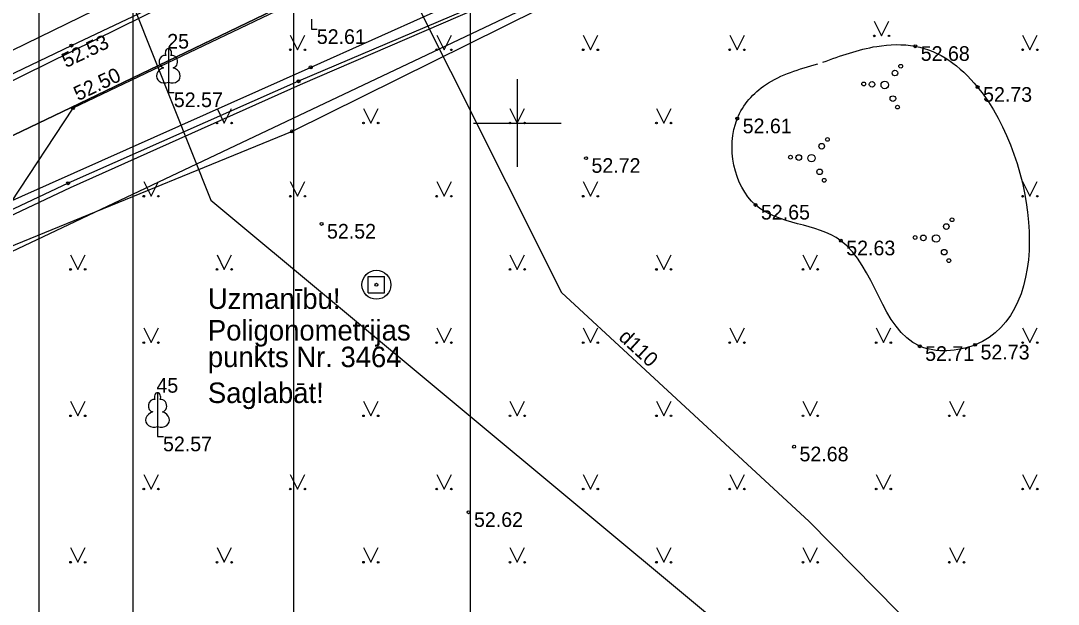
# Model space of a CAD drawing. Extents: x 619806 to 620082, y 405176 to 405386.
# Drawn here: x 619933.05 to 619968.46, y 405333.56 to 405353.49 of the extents above; entities that cross this region are included whole.
import ezdxf

# ---------------------------------------------------------------- set-up
doc = ezdxf.new("R2010")
doc.units = 0
for name, color, linetype in [('24', 7, 'Continuous'), ('APGR_SARK_####_####_#', 7, 'Continuous'), ('APGS_VADP_ZSPR_####_#', 7, 'Continuous'), ('CELI_CMAL_####_####_#', 7, 'Continuous'), ('ELEK_VADP_ZSPR_####_#', 7, 'Continuous'), ('GEOD_ELEM_####_####_#', 7, 'Continuous'), ('GEOD_ELEM_####_TKST_#', 7, 'Continuous'), ('RAMI_PLAN_####_TKST_#', 7, 'Continuous'), ('RAMI_UZMR_####_####_#', 7, 'Continuous'), ('RELJ_AATZ_####_TKST_#', 7, 'Continuous'), ('RELJ_ELEM_####_####_#', 7, 'Continuous'), ('ROBZ_UZMR_####_####_#', 7, 'Continuous'), ('SAKT_VADP_KABE_####_#', 7, 'Continuous'), ('TERT_DIAM_####_TKST_#', 7, 'Continuous'), ('TERT_ELEM_####_####_#', 7, 'Continuous'), ('TERT_KONT_####_####_#', 7, 'Continuous'), ('UDTK_VADP_UDEN_####_#', 7, 'Continuous'), ('UDTK_VADP_UDEN_TKST_#', 7, 'Continuous')]:
    doc.layers.add(name, color=color, linetype=linetype)

msp = doc.modelspace()

# ---------------------------------------------------------------- linework, layer by layer
at = {"layer": '24'}
for p, q in [((619962.326, 405363.803), (619934.749, 405350.522)), ((619934.749, 405350.522), (619931.837, 405349.12))]:
    msp.add_line(p, q, dxfattribs=at)
at = {"layer": 'APGR_SARK_####_####_#'}
msp.add_lwpolyline([(619818.56, 405291.467), (619964.609, 405360.731), (619976.198, 405343.424)], dxfattribs=at)
at = {"layer": 'APGS_VADP_ZSPR_####_#'}
for points in [[(619961.504, 405361.726), (619961.549, 405360.889), (619955.561, 405357.47), (619948.629, 405353.911), (619942.586, 405351.309), (619934.737, 405347.784), (619926.308, 405343.807), (619921.62, 405341.722), (619914.616, 405338.589), (619904.064, 405332.419), (619892.947, 405327.707), (619882.253, 405322.432), (619872.343, 405318.394), (619866.043, 405315.914), (619858.147, 405313.031), (619849.141, 405308.474), (619837.591, 405302.476), (619829.867, 405298.738), (619827.533, 405297.619), (619826.332, 405294.789), (619825.868, 405290.973), (619826.009, 405290.873), (619827.279, 405290.766)], [(619961.504, 405361.726), (619961.582, 405360.944), (619961.547, 405359.255), (619942.312, 405349.715), (619925.4, 405342.794), (619907.997, 405333.971), (619887.51, 405324.581), (619867.415, 405316.417), (619859.827, 405308.06), (619845.28, 405301.51), (619837.164, 405301.798), (619827.1, 405298.963), (619826.475, 405294.709), (619826.025, 405290.988), (619827.279, 405290.766)], [(619961.504, 405361.726), (619961.513, 405360.941), (619956.997, 405358.363), (619948.588, 405354.007), (619942.536, 405351.427), (619934.667, 405347.943), (619926.276, 405343.988), (619921.568, 405341.876), (619914.639, 405338.805), (619913.878, 405339.748), (619914.447, 405338.686), (619904.019, 405332.565), (619892.911, 405327.951)]]:
    msp.add_lwpolyline(points, dxfattribs=at)
at = {"layer": 'CELI_CMAL_####_####_#'}
for points in [[(619991.854, 405321.355), (619987.265, 405327.894), (619980.195, 405338.024), (619973.089, 405348.264), (619967.033, 405357.029), (619962.383, 405363.658), (619953.25, 405359.322), (619947.967, 405356.794), (619934.832, 405350.507), (619928.431, 405340.813), (619925.67, 405336.505), (619926.565, 405335.935), (619923.8, 405331.651)], [(619825.042, 405301.626), (619825.997, 405300.736), (619826.865, 405300.888), (619837.411, 405305.982), (619845.924, 405310.094), (619856.691, 405315.252), (619868.203, 405320.761), (619880.848, 405326.828), (619891.162, 405331.79), (619903.487, 405337.685), (619914.792, 405343.079), (619924.282, 405347.611), (619934.782, 405352.643), (619943.391, 405356.735), (619942.998, 405357.499)]]:
    msp.add_lwpolyline(points, dxfattribs=at)
at = {"layer": 'ELEK_VADP_ZSPR_####_#'}
msp.add_lwpolyline([(619971.958, 405366.357), (619953.365, 405356.579), (619942.947, 405351.901), (619927.707, 405345.105), (619922.312, 405345.694), (619917.565, 405346.118)], dxfattribs=at)
at = {"layer": 'GEOD_ELEM_####_####_#'}
for p, q in [((619950, 405351.5), (619950, 405350)), ((619948.5, 405350), (619950, 405350)), ((619950, 405350), (619950, 405348.5)), ((619950, 405350), (619951.5, 405350)), ((619944.909, 405344.756), (619945.47, 405344.756)), ((619944.909, 405344.195), (619944.909, 405344.756)), ((619945.47, 405344.195), (619945.47, 405344.756)), ((619944.909, 405344.195), (619945.47, 405344.195))]:
    msp.add_line(p, q, dxfattribs=at)
for radius in [0.495, 0.05]:
    msp.add_circle((619945.19, 405344.475), radius, dxfattribs=at)
at = {"layer": 'RAMI_PLAN_####_TKST_#'}
msp.add_line((619942.357, 405361.716), (619942.357, 405215.404), dxfattribs=at)
for points in [[(619933.685, 405385.595), (620082.185, 405385.595), (620082.185, 405175.595), (619933.685, 405175.595)], [(619805.793, 405180.095), (619805.793, 405373.209), (619948.393, 405373.209), (619948.393, 405180.095)], [(619936.885, 405180.095), (619936.885, 405373.209), (620079.485, 405373.209), (620079.485, 405180.095)]]:
    msp.add_lwpolyline(points, close=True, dxfattribs=at)
at = {"layer": 'RAMI_UZMR_####_####_#'}
msp.add_lwpolyline([(619874.687, 405324.979), (619926.719, 405349.544), (619966.669, 405369.042), (620021.738, 405292.03), (620049.703, 405275.476), (620026.189, 405242.287), (620012.147, 405222.917), (619996.603, 405200.928), (619989.997, 405199.173), (619982.328, 405199.155), (619922.669, 405233.014), (619882.137, 405255.756), (619859.084, 405268.056), (619820.646, 405290.715), (619813.744, 405295.206), (619820.645, 405298.752)], close=True, dxfattribs=at)
at = {"layer": 'RELJ_ELEM_####_####_#'}
for centre in [(619934.782, 405352.643), (619963.585, 405352.623), (619942.947, 405351.901), (619942.536, 405351.427), (619965.713, 405351.226), (619934.832, 405350.507), (619957.508, 405350.15), (619942.312, 405349.715), (619952.346, 405348.799), (619934.667, 405347.943), (619958.131, 405347.204), (619943.318, 405346.554), (619961.043, 405345.982), (619963.736, 405342.377), (619965.627, 405342.425), (619959.447, 405338.946), (619948.336, 405336.706)]:
    msp.add_circle(centre, 0.05, dxfattribs=at)
at = {"layer": 'ROBZ_UZMR_####_####_#'}
for p, q in [((619934.749, 405350.522), (619962.326, 405363.803)), ((619931.837, 405349.12), (619934.749, 405350.522))]:
    msp.add_line(p, q, dxfattribs=at)
at = {"layer": 'SAKT_VADP_KABE_####_#'}
for points in [[(619816.151, 405294.73), (619838.42, 405305.23), (619866.149, 405318.697), (619899.278, 405334.929), (619937.202, 405353.635), (619962.924, 405366.289), (619964.424, 405369.208)], [(619935.629, 405357.201), (619939.538, 405347.363), (619973.032, 405319.457), (620006.975, 405291.595), (620036.262, 405267.248), (620043.553, 405261.241)]]:
    msp.add_lwpolyline(points, dxfattribs=at)
at = {"layer": 'TERT_ELEM_####_####_#'}
for p, q in [((619942.971, 405353.548), (619942.971, 405353.201)), ((619962.186, 405353.476), (619962.436, 405352.976)), ((619962.436, 405352.976), (619962.686, 405353.476)), ((619942.971, 405353.201), (619943.171, 405353.201)), ((619942.25, 405353), (619942.5, 405352.5)), ((619942.5, 405352.5), (619942.75, 405353)), ((619947.25, 405353), (619947.5, 405352.5)), ((619947.5, 405352.5), (619947.75, 405353)), ((619952.25, 405353), (619952.5, 405352.5)), ((619952.5, 405352.5), (619952.75, 405353)), ((619957.25, 405353), (619957.5, 405352.5)), ((619957.5, 405352.5), (619957.75, 405353)), ((619967.25, 405353), (619967.5, 405352.5)), ((619967.5, 405352.5), (619967.75, 405353)), ((619938.09, 405351.39), (619938.09, 405351.043)), ((619938.09, 405351.043), (619938.29, 405351.043)), ((619939.75, 405350.5), (619940, 405350)), ((619940, 405350), (619940.25, 405350.5)), ((619944.75, 405350.5), (619945, 405350)), ((619945, 405350), (619945.25, 405350.5)), ((619949.75, 405350.5), (619950, 405350)), ((619950, 405350), (619950.25, 405350.5)), ((619954.75, 405350.5), (619955, 405350)), ((619955, 405350), (619955.25, 405350.5)), ((619937.25, 405348), (619937.5, 405347.5)), ((619937.5, 405347.5), (619937.75, 405348)), ((619942.25, 405348), (619942.5, 405347.5)), ((619942.5, 405347.5), (619942.75, 405348)), ((619947.25, 405348), (619947.5, 405347.5)), ((619947.5, 405347.5), (619947.75, 405348)), ((619952.25, 405348), (619952.5, 405347.5)), ((619952.5, 405347.5), (619952.75, 405348)), ((619967.25, 405348), (619967.5, 405347.5)), ((619967.5, 405347.5), (619967.75, 405348)), ((619934.75, 405345.5), (619935, 405345)), ((619935, 405345), (619935.25, 405345.5)), ((619939.75, 405345.5), (619940, 405345)), ((619940, 405345), (619940.25, 405345.5)), ((619949.75, 405345.5), (619950, 405345)), ((619950, 405345), (619950.25, 405345.5)), ((619954.75, 405345.5), (619955, 405345)), ((619955, 405345), (619955.25, 405345.5)), ((619959.75, 405345.5), (619960, 405345)), ((619960, 405345), (619960.25, 405345.5)), ((619937.25, 405343), (619937.5, 405342.5)), ((619937.5, 405342.5), (619937.75, 405343)), ((619947.25, 405343), (619947.5, 405342.5)), ((619947.5, 405342.5), (619947.75, 405343)), ((619952.25, 405343), (619952.5, 405342.5)), ((619952.5, 405342.5), (619952.75, 405343)), ((619957.25, 405343), (619957.5, 405342.5)), ((619957.5, 405342.5), (619957.75, 405343)), ((619962.25, 405343), (619962.5, 405342.5)), ((619962.5, 405342.5), (619962.75, 405343)), ((619967.25, 405343), (619967.5, 405342.5)), ((619967.5, 405342.5), (619967.75, 405343)), ((619934.75, 405340.5), (619935, 405340)), ((619935, 405340), (619935.25, 405340.5)), ((619944.75, 405340.5), (619945, 405340)), ((619945, 405340), (619945.25, 405340.5)), ((619949.75, 405340.5), (619950, 405340)), ((619950, 405340), (619950.25, 405340.5)), ((619954.75, 405340.5), (619955, 405340)), ((619955, 405340), (619955.25, 405340.5)), ((619959.75, 405340.5), (619960, 405340)), ((619960, 405340), (619960.25, 405340.5)), ((619964.75, 405340.5), (619965, 405340)), ((619965, 405340), (619965.25, 405340.5)), ((619937.721, 405339.637), (619937.721, 405339.29)), ((619937.721, 405339.29), (619937.921, 405339.29)), ((619937.25, 405338), (619937.5, 405337.5)), ((619937.5, 405337.5), (619937.75, 405338)), ((619942.25, 405338), (619942.5, 405337.5)), ((619942.5, 405337.5), (619942.75, 405338)), ((619947.25, 405338), (619947.5, 405337.5)), ((619947.5, 405337.5), (619947.75, 405338)), ((619952.25, 405338), (619952.5, 405337.5)), ((619952.5, 405337.5), (619952.75, 405338)), ((619957.25, 405338), (619957.5, 405337.5)), ((619957.5, 405337.5), (619957.75, 405338)), ((619962.25, 405338), (619962.5, 405337.5)), ((619962.5, 405337.5), (619962.75, 405338)), ((619967.25, 405338), (619967.5, 405337.5)), ((619967.5, 405337.5), (619967.75, 405338)), ((619934.75, 405335.5), (619935, 405335)), ((619935, 405335), (619935.25, 405335.5)), ((619939.75, 405335.5), (619940, 405335)), ((619940, 405335), (619940.25, 405335.5)), ((619944.75, 405335.5), (619945, 405335)), ((619945, 405335), (619945.25, 405335.5)), ((619949.75, 405335.5), (619950, 405335)), ((619950, 405335), (619950.25, 405335.5)), ((619954.75, 405335.5), (619955, 405335)), ((619955, 405335), (619955.25, 405335.5)), ((619959.75, 405335.5), (619960, 405335)), ((619960, 405335), (619960.25, 405335.5)), ((619964.75, 405335.5), (619965, 405335)), ((619965, 405335), (619965.25, 405335.5))]:
    msp.add_line(p, q, dxfattribs=at)
for points in [[(619938.09, 405352.543), (619938.09, 405351.39)], [(619938.18, 405352.311), (619938.179, 405352.312)], [(619937.721, 405340.79), (619937.721, 405339.637)], [(619937.811, 405340.558), (619937.81, 405340.559)]]:
    msp.add_lwpolyline(points, dxfattribs=at)
for centre, radius in [((619962.186, 405352.976), 0.028), ((619962.686, 405352.976), 0.0263), ((619942.25, 405352.5), 0.028), ((619942.75, 405352.5), 0.0263), ((619947.25, 405352.5), 0.028), ((619947.75, 405352.5), 0.0263), ((619952.25, 405352.5), 0.028), ((619952.75, 405352.5), 0.0263), ((619957.25, 405352.5), 0.028), ((619957.75, 405352.5), 0.0263), ((619967.25, 405352.5), 0.028), ((619967.75, 405352.5), 0.0263), ((619963.087, 405351.939), 0.064), ((619962.891, 405351.707), 0.096), ((619961.825, 405351.334), 0.064), ((619962.109, 405351.321), 0.096), ((619962.543, 405351.3), 0.128), ((619962.82, 405350.833), 0.096), ((619962.977, 405350.544), 0.064), ((619939.75, 405350), 0.028), ((619940.25, 405350), 0.0263), ((619944.75, 405350), 0.028), ((619945.25, 405350), 0.0263), ((619949.75, 405350), 0.028), ((619950.25, 405350), 0.0263), ((619954.75, 405350), 0.028), ((619955.25, 405350), 0.0263), ((619960.587, 405349.439), 0.064), ((619960.391, 405349.207), 0.096), ((619959.325, 405348.834), 0.064), ((619959.609, 405348.821), 0.096), ((619960.043, 405348.8), 0.128), ((619960.32, 405348.333), 0.096), ((619960.477, 405348.044), 0.064), ((619937.25, 405347.5), 0.028), ((619937.75, 405347.5), 0.0263), ((619942.25, 405347.5), 0.028), ((619942.75, 405347.5), 0.0263), ((619947.25, 405347.5), 0.028), ((619947.75, 405347.5), 0.0263), ((619952.25, 405347.5), 0.028), ((619952.75, 405347.5), 0.0263), ((619967.25, 405347.5), 0.028), ((619967.75, 405347.5), 0.0263), ((619964.84, 405346.696), 0.064), ((619964.644, 405346.465), 0.096), ((619963.578, 405346.091), 0.064), ((619963.862, 405346.078), 0.096), ((619964.296, 405346.057), 0.128), ((619964.572, 405345.59), 0.096), ((619964.73, 405345.301), 0.064), ((619934.75, 405345), 0.028), ((619935.25, 405345), 0.0263), ((619939.75, 405345), 0.028), ((619940.25, 405345), 0.0263), ((619949.75, 405345), 0.028), ((619950.25, 405345), 0.0263), ((619954.75, 405345), 0.028), ((619955.25, 405345), 0.0263), ((619959.75, 405345), 0.028), ((619960.25, 405345), 0.0263), ((619937.25, 405342.5), 0.028), ((619937.75, 405342.5), 0.0263), ((619947.25, 405342.5), 0.028), ((619947.75, 405342.5), 0.0263), ((619952.25, 405342.5), 0.028), ((619952.75, 405342.5), 0.0263), ((619957.25, 405342.5), 0.028), ((619957.75, 405342.5), 0.0263), ((619962.25, 405342.5), 0.028), ((619962.75, 405342.5), 0.0263), ((619967.25, 405342.5), 0.028), ((619967.75, 405342.5), 0.0263), ((619934.75, 405340), 0.028), ((619935.25, 405340), 0.0263), ((619944.75, 405340), 0.028), ((619945.25, 405340), 0.0263), ((619949.75, 405340), 0.028), ((619950.25, 405340), 0.0263), ((619954.75, 405340), 0.028), ((619955.25, 405340), 0.0263), ((619959.75, 405340), 0.028), ((619960.25, 405340), 0.0263), ((619964.75, 405340), 0.028), ((619965.25, 405340), 0.0263), ((619937.25, 405337.5), 0.028), ((619937.75, 405337.5), 0.0263), ((619942.25, 405337.5), 0.028), ((619942.75, 405337.5), 0.0263), ((619947.25, 405337.5), 0.028), ((619947.75, 405337.5), 0.0263), ((619952.25, 405337.5), 0.028), ((619952.75, 405337.5), 0.0263), ((619957.25, 405337.5), 0.028), ((619957.75, 405337.5), 0.0263), ((619962.25, 405337.5), 0.028), ((619962.75, 405337.5), 0.0263), ((619967.25, 405337.5), 0.028), ((619967.75, 405337.5), 0.0263), ((619934.75, 405335), 0.028), ((619935.25, 405335), 0.0263), ((619939.75, 405335), 0.028), ((619940.25, 405335), 0.0263), ((619944.75, 405335), 0.028), ((619945.25, 405335), 0.0263), ((619949.75, 405335), 0.028), ((619950.25, 405335), 0.0263), ((619954.75, 405335), 0.028), ((619955.25, 405335), 0.0263), ((619959.75, 405335), 0.028), ((619960.25, 405335), 0.0263), ((619964.75, 405335), 0.028), ((619965.25, 405335), 0.0263)]:
    msp.add_circle(centre, radius, dxfattribs=at)
for centre, major_axis, ratio, start_param, end_param in [((619937.962, 405352.098), (-0.039, -0.212), 0.861323, 3.141593, 6.283185), ((619938.09, 405352.393), (0, -0.15), 0.707107, 3.14537, 5.287485), ((619938.09, 405352.393), (0, -0.15), 0.707107, 0.995701, 3.137816), ((619938.218, 405352.098), (0.039, -0.212), 0.861323, 0, 3.141593), ((619938, 405351.636), (0.307, 0.095), 0.814445, 1.570796, 4.752015), ((619938.18, 405351.636), (-0.307, 0.095), 0.814445, 1.531171, 4.712389), ((619937.721, 405340.64), (0, -0.15), 0.707107, 3.14537, 5.287485), ((619937.721, 405340.64), (0, -0.15), 0.707107, 0.995701, 3.137816), ((619937.593, 405340.345), (-0.039, -0.212), 0.861323, 3.141593, 6.283185), ((619937.849, 405340.345), (0.039, -0.212), 0.861323, 0, 3.141593), ((619937.631, 405339.883), (0.307, 0.095), 0.814445, 1.570796, 4.752015), ((619937.811, 405339.883), (-0.307, 0.095), 0.814445, 1.531171, 4.712389)]:
    msp.add_ellipse(centre, major_axis=major_axis, ratio=ratio, start_param=start_param, end_param=end_param, dxfattribs=at)
at = {"layer": 'TERT_KONT_####_####_#'}
msp.add_spline([(619960.429, 405352.076), (619962.267, 405352.617), (619963.585, 405352.623), (619965.713, 405351.226), (619965.627, 405342.425), (619963.736, 405342.377), (619961.043, 405345.982), (619958.131, 405347.204), (619957.508, 405350.15), (619958.477, 405351.308), (619960.254, 405352.018)], degree=3, dxfattribs=at)
at = {"layer": 'UDTK_VADP_UDEN_####_#'}
msp.add_lwpolyline([(619945.834, 405355.555), (619951.504, 405344.209), (619959.966, 405336.395), (619975.103, 405321.007), (620000.001, 405300.143)], dxfattribs=at)

# ---------------------------------------------------------------- texts
at = {"layer": 'GEOD_ELEM_####_TKST_#'}
for s, p in [('Uzmanību!', (619939.439, 405343.652)), ('Poligonometrijas', (619939.439, 405342.572)), ('punkts Nr. 3464', (619939.439, 405341.662)), ('Saglabāt!', (619939.439, 405340.437))]:
    msp.add_text(s, height=0.7, dxfattribs=at).set_placement(p)
at = {"layer": 'RELJ_AATZ_####_TKST_#'}
for s, p in [(' 52.61', (619942.971, 405352.701)), (' 52.68', (619963.585, 405352.123)), (' 52.57', (619938.09, 405350.543)), (' 52.73', (619965.713, 405350.726)), (' 52.61', (619957.508, 405349.65)), (' 52.72', (619952.346, 405348.299)), (' 52.65', (619958.131, 405346.704)), (' 52.52', (619943.318, 405346.054)), (' 52.63', (619961.043, 405345.482)), (' 52.73', (619965.627, 405341.925)), (' 52.71', (619963.736, 405341.877)), (' 52.57', (619937.721, 405338.79)), (' 52.68', (619959.447, 405338.446)), (' 52.62', (619948.336, 405336.206))]:
    msp.add_text(s, height=0.5, dxfattribs=at).set_placement(p)
for s, rotation, p in [(' 52.53', 25.4225, (619934.431, 405351.794)), (' 52.50', 25.5779, (619934.84, 405350.662))]:
    msp.add_text(s, height=0.5, rotation=rotation, dxfattribs=at).set_placement(p)
at = {"layer": 'TERT_DIAM_####_TKST_#'}
for s, p in [(' 25', (619937.865, 405352.543)), (' 45', (619937.496, 405340.79))]:
    msp.add_text(s, height=0.5, dxfattribs=at).set_placement(p)
at = {"layer": 'UDTK_VADP_UDEN_TKST_#'}
msp.add_text('d110', height=0.5, rotation=317.2799, dxfattribs=at).set_placement((619953.425, 405342.64))

doc.saveas('drawing.dxf')
